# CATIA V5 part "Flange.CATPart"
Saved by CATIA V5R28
Part number: Flange
Material "Bright Orange": density 7860 kg/m3, Young's modulus 2e+11 Pa, Poisson ratio 0.266
Bounding box of the stored display mesh (mm): x -35 to 35, y 0 to 35, z -35 to 35
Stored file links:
  C:\Users\Parisa\Desktop\tarah sanat\Oldham Coupling\Flange.CATPart
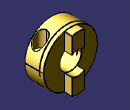
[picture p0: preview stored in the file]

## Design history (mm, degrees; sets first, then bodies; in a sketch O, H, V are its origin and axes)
Body1 (main body), material "Bright Orange"
  Sketch1 on zx-plane, origin (0, 0, 0), H (-1, 0, 0), V (0, 0, 1)
    circle A1 centre (0, 0) radius 35
    circle A2 centre (0, 0) radius 14
    radius A1 = 35
    radius A2 = 14
  Pad1: profile Sketch1, direction (0, 1, 0), length 25
  Chamfer1: length 0.5, angle 45, on edge [face of Pad1 from Sketch1.A1 | end face of Pad1]; edge [end face of Pad1 | face of Pad1 from Sketch1.A2]; edge [start face of Pad1 | face of Pad1 from Sketch1.A1]; start face of Pad1
  Sketch2 on end face of Pad1, origin (0, 25, 0), H (-1, 0, 0), V (0, 0, 1)
    projected circle E1 centre (0, 0) radius 14.5 from edge [end face of Pad1 | face of Chamfer1]
    projected arc E2 centre (0, 0) radius 14.5 from (8.25, 11.9242) to (-8.25, 11.9242) ccw from edge [end face of Pad1 | face of Chamfer1]
    projected circle E3 centre (0, 0) radius 35 from edge [face of Pad1 from Sketch1.A1 | face of Chamfer1]
    projected arc E4 centre (0, 0) radius 35 from (8.25, 34.0138) to (-8.25, 34.0138) ccw from edge [face of Pad1 from Sketch1.A1 | face of Chamfer1]
    point P1 (0, 24.1208)
    line L1 (8.25, 34.0138) -> (8.25, 11.9242)
    line L2 (-8.25, 11.9242) -> (-8.25, 34.0138)
    point P2 (8.25, 34.0138)
    point P3 (-8.25, 34.0138)
    point P4 (8.25, 11.9242)
    point P5 (-8.25, 11.9242)
    distance L1 L2 = 16.5
    coincidence: P1 V, E3 P2, E3 P3, E1 P4, E1 P5
    vertical: L1 V, L2 V
    equidistance: L1 L2 P1
  Pad2: profile Sketch2, direction (0, 1, 0), length 10
  Chamfer2: length 0.5, angle 45, on end face of Pad2; face of Pad2 from Sketch2.E4; edge [face of Pad2 from Sketch2.L1 | face of Pad2 from Sketch2.E2]; edge [face of Pad2 from Sketch2.E2 | face of Pad2 from Sketch2.L2]
  Mirror1: of Pad2, Chamfer2, about xy-plane
  Plane1: type Offset, RefPlane xy-plane, Offset 10
  Sketch3 on Plane1, origin (0, 0, 10), H (1, 0, 0), V (0, 1, 0)
    circle A1 centre (23, 9) radius 7.5
    point P1 (23, 9)
    reference projected line E1 through (0, 0) direction (0, 1) from axis of face of Pad1 from Sketch1.A1
    radius A1 = 7.5
    distance E1 P1 = 23
    distance P1 H = 9
  Pocket1: profile Sketch3, direction (0, 0, 1), through (limit type 3)
  Sketch4 on start face of Pocket1, origin (0, 0, 10), H (1, 0, 0), V (0, 1, 0)
    circle A1 centre (23, 9) radius 4
    reference projected circle E1 centre (23, 9) radius 7.5 from edge [face of Pad1 from Sketch1.A1 | face of Pocket1 from Sketch3.A1]
    radius A1 = 4
    concentricity: A1 E1
  Pocket2: profile Sketch4, direction (0, 0, -1), through (limit type 3)
  Sketch5 on start face of Pad1, origin (0, 0, 0), H (1, 0, 0), V (0, 0, 1)
    point P1 (2.5, 0)
    line L1 (35, 0.5) -> (35, -0.5)
    line L2 (35, -0.5) -> (-30, -0.5)
    line L3 (-30, -0.5) -> (-30, 0.5)
    line L4 (-30, 0.5) -> (35, 0.5)
    reference projected circle E1 centre (0, 0) radius 35 from edge [face of Chamfer1 | face of Pad1 from Sketch1.A1]
    reference projected circle E2 centre (0, 0) radius 35 from edge [face of Chamfer1 | face of Pad1 from Sketch1.A1]
    distance L3 E1 = 5
    distance L2 L4 = 1
    coincidence: P1 H
    vertical: L1 V, L3 V
    horizontal: L2 H, L4 H
    equidistance: L1 L3 P1, L2 L4 P1
    tangency: L1 E2
  Pocket3: profile Sketch5, direction (0, 1, 0), length 20
  Sketch6 on yz-plane, origin (0, 0, 0), H (0, 1, 0), V (0, 0, 1)
    reference projected line E2 (0.5, 35) -> (24.5, 35) from face of Pad1 from Sketch1.A1
    point P5 (20, 35)
    line L1 (20, 35) -> (19, 35)
    line L2 (19, 35) -> (19, -5.5)
    line L3 (19, -5.5) -> (20, -5.5)
    line L4 (20, -5.5) -> (20, 35)
    reference projected line E3 (20, -0.5) -> (20, 0.5) from edge [face of Pad1 from Sketch1.A1 | end face of Pocket3]
    reference projected line E4 (0.5, -0.5) -> (20, -0.5) from edge [face of Pad1 from Sketch1.A1 | face of Pocket3 from Sketch5.L2]
    distance L2 L4 = 1
    distance L3 E4 = 5
    coincidence: P5 E2, E3 L4
    horizontal: L1 H, L3 H
    vertical: L2 V, L4 V
  Pocket4: profile Sketch6, direction (-1, 0, 0), through (limit type 3), opposite side through (limit type 3)
  Fillet1: radius 0.5, on edge [face of Pad1 from Sketch1.A1 | face of Pocket1 from Sketch3.A1]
